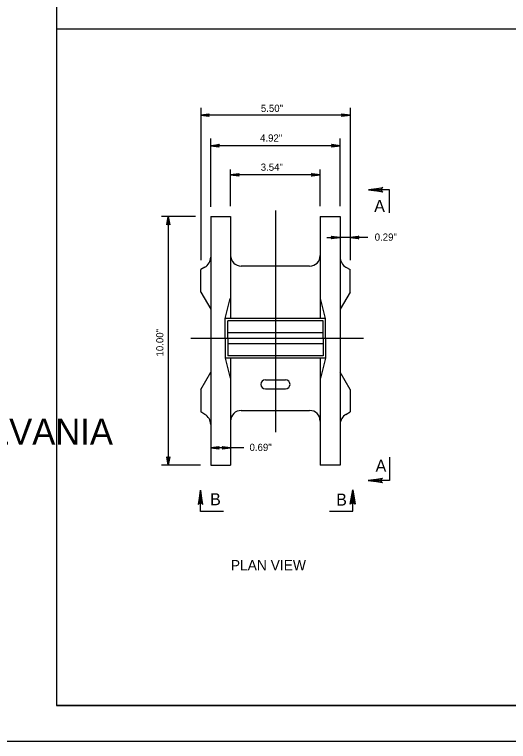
# Model space of a CAD drawing. Extents: x 639362 to 641108, y 298458 to 299646.
# Drawn here: x 640225.9 to 640431.7, y 298457.6 to 298760.6 of the extents above; entities that cross this region are included whole.
import ezdxf

# ---------------------------------------------------------------- set-up
doc = ezdxf.new("R2010")
doc.units = 0
for name, color, linetype in [('1', 7, 'Continuous'), ('2', 7, 'Continuous'), ('3', 7, 'Continuous'), ('PLT-BNDY', 7, 'Continuous')]:
    doc.layers.add(name, color=color, linetype=linetype)

# ---------------------------------------------------------------- blocks, each defined once
blk = doc.blocks.new('RARROW')
at = {"layer": '3'}
blk.add_lwpolyline([(-2.2695, 0.285), (-2.184875, 0.12075), (0, 0), (-2.2695, 0.285), (-2.38575, 0.384625), (0, 0), (-2.183125, -0.108), (-2.262875, -0.2705), (0, 0), (-2.38575, -0.379125), (-2.262875, -0.2705)], dxfattribs=at)

msp = doc.modelspace()

# ---------------------------------------------------------------- linework, layer by layer
at = {"layer": '1'}
for p, q in [((640243.31, 299036.63), (640243.31, 298472.63)), ((640243.31, 298754.63), (640829.31, 298754.63)), ((641029.31, 298472.63), (640243.31, 298472.63)), ((640243.31, 298472.63), (640829.31, 298472.63))]:
    msp.add_line(p, q, dxfattribs=at)
at = {"layer": '2'}
for p, q in [((640303.46, 298721.7), (640303.46, 298658.32)), ((640365.72, 298721.7), (640365.72, 298658.32)), ((640365.72, 298718.7), (640303.46, 298718.7)), ((640307.61, 298680.52), (640307.61, 298708.97)), ((640361.56, 298680.82), (640361.56, 298708.97)), ((640361.56, 298705.97), (640307.61, 298705.97)), ((640315.91, 298680.82), (640315.91, 298696.07)), ((640353.26, 298680.82), (640353.26, 298696.07)), ((640353.26, 298693.8), (640315.91, 298693.8)), ((640382.2, 298687.58), (640373.32, 298687.58)), ((640382.2, 298677.95), (640382.2, 298687.58)), ((640334.59, 298678.97), (640334.59, 298586.59)), ((640301.31, 298676.52), (640287.16, 298676.52)), ((640289.95, 298676.52), (640289.95, 298572.76)), ((640307.61, 298676.52), (640307.61, 298572.76)), ((640307.61, 298676.52), (640315.91, 298676.52)), ((640315.91, 298676.52), (640315.91, 298633.98)), ((640353.26, 298676.52), (640361.56, 298676.52)), ((640353.26, 298676.52), (640353.26, 298633.98)), ((640361.56, 298676.52), (640361.56, 298572.76)), ((640355.97, 298667.66), (640361.4, 298667.66)), ((640365.72, 298667.66), (640361.64, 298667.66)), ((640373.13, 298667.66), (640365.72, 298667.66)), ((640305.17, 298655.31), (640303.46, 298654.32)), ((640348.84, 298655.77), (640320.34, 298655.77)), ((640364, 298655.31), (640365.72, 298654.32)), ((640303.46, 298644.96), (640303.46, 298654.32)), ((640365.72, 298644.96), (640365.72, 298654.32)), ((640303.46, 298644.96), (640307.61, 298637.77)), ((640365.72, 298644.96), (640361.56, 298637.77)), ((640313.66, 298633.98), (640315.77, 298642.33)), ((640355.51, 298633.98), (640353.4, 298642.33)), ((640355.51, 298633.98), (640313.66, 298633.98)), ((640313.66, 298625.68), (640313.66, 298633.98)), ((640355.51, 298625.68), (640355.51, 298633.98)), ((640314.72, 298625.68), (640314.72, 298632.99)), ((640354.46, 298632.99), (640314.72, 298632.99)), ((640354.46, 298625.68), (640354.46, 298632.99)), ((640354.46, 298628.01), (640314.72, 298628.01)), ((640299.32, 298625.68), (640371.31, 298625.68)), ((640313.66, 298625.68), (640313.66, 298617.38)), ((640314.72, 298625.68), (640314.72, 298618.38)), ((640354.46, 298625.68), (640354.46, 298618.38)), ((640355.51, 298625.68), (640355.51, 298617.38)), ((640354.46, 298623.36), (640314.72, 298623.36)), ((640354.46, 298618.38), (640314.72, 298618.38)), ((640355.51, 298617.38), (640313.66, 298617.38)), ((640313.66, 298617.38), (640315.77, 298609.04)), ((640315.91, 298617.38), (640315.91, 298572.76)), ((640353.26, 298617.38), (640353.26, 298572.76)), ((640355.51, 298617.38), (640353.4, 298609.04)), ((640303.46, 298604.32), (640307.61, 298611.52)), ((640365.72, 298604.32), (640361.56, 298611.52)), ((640330.41, 298608.39), (640338.77, 298608.39)), ((640303.46, 298604.32), (640303.46, 298594.97)), ((640330.41, 298604.58), (640338.77, 298604.58)), ((640365.72, 298604.32), (640365.72, 298594.97)), ((640305.17, 298593.98), (640303.46, 298594.97)), ((640320.34, 298595.59), (640348.84, 298595.59)), ((640364, 298593.98), (640365.72, 298594.97)), ((640315.91, 298580.01), (640307.61, 298580.01)), ((640321.42, 298580.01), (640315.91, 298580.01)), ((640382.08, 298576.2), (640382.08, 298566.45)), ((640303.31, 298572.76), (640287.16, 298572.76)), ((640307.61, 298572.76), (640315.91, 298572.76)), ((640361.56, 298572.76), (640353.26, 298572.76)), ((640382.08, 298566.45), (640373.2, 298566.45)), ((640303.35, 298553.53), (640303.35, 298562.4)), ((640366.8, 298553.68), (640366.8, 298562.56)), ((640312.97, 298553.53), (640303.35, 298553.53)), ((640357.17, 298553.68), (640366.8, 298553.68))]:
    msp.add_line(p, q, dxfattribs=at)
for points in [[(640306.86, 298718.27), (640306.74, 298718.52), (640303.46, 298718.7), (640306.86, 298718.27), (640307.04, 298718.12), (640303.46, 298718.7), (640306.73, 298718.86), (640306.85, 298719.1), (640303.46, 298718.7), (640307.04, 298719.27), (640306.85, 298719.1)], [(640362.31, 298719.12), (640362.44, 298718.88), (640365.72, 298718.7), (640362.31, 298719.12), (640362.14, 298719.27), (640365.72, 298718.7), (640362.44, 298718.53), (640362.32, 298718.29), (640365.72, 298718.7), (640362.14, 298718.13), (640362.32, 298718.29)], [(640311.01, 298705.54), (640310.89, 298705.79), (640307.61, 298705.97), (640311.01, 298705.54), (640311.19, 298705.39), (640307.61, 298705.97), (640310.88, 298706.13), (640311, 298706.38), (640307.61, 298705.97), (640311.19, 298706.54), (640311, 298706.38)], [(640358.16, 298706.4), (640358.29, 298706.15), (640361.56, 298705.97), (640358.16, 298706.4), (640357.98, 298706.54), (640361.56, 298705.97), (640358.29, 298705.81), (640358.17, 298705.56), (640361.56, 298705.97), (640357.98, 298705.4), (640358.17, 298705.56)], [(640319.32, 298693.37), (640319.19, 298693.62), (640315.91, 298693.8), (640319.32, 298693.37), (640319.49, 298693.22), (640315.91, 298693.8), (640319.19, 298693.96), (640319.3, 298694.2), (640315.91, 298693.8), (640319.49, 298694.37), (640319.3, 298694.2)], [(640349.86, 298694.22), (640349.99, 298693.98), (640353.26, 298693.8), (640349.86, 298694.22), (640349.68, 298694.37), (640353.26, 298693.8), (640349.99, 298693.63), (640349.87, 298693.39), (640353.26, 298693.8), (640349.68, 298693.23), (640349.87, 298693.39)], [(640289.52, 298673.12), (640289.77, 298673.24), (640289.95, 298676.52), (640289.52, 298673.12), (640289.38, 298672.94), (640289.95, 298676.52), (640290.12, 298673.25), (640290.36, 298673.13), (640289.95, 298676.52), (640290.52, 298672.94), (640290.36, 298673.13)], [(640358, 298668.08), (640358.12, 298667.84), (640361.4, 298667.66), (640358, 298668.08), (640357.82, 298668.23), (640361.4, 298667.66), (640358.13, 298667.49), (640358.01, 298667.25), (640361.4, 298667.66), (640357.82, 298667.09), (640358.01, 298667.25)], [(640369.12, 298667.23), (640369, 298667.48), (640365.72, 298667.66), (640369.12, 298667.23), (640369.3, 298667.08), (640365.72, 298667.66), (640368.99, 298667.82), (640369.11, 298668.06), (640365.72, 298667.66), (640369.3, 298668.23), (640369.11, 298668.06)], [(640311.01, 298579.58), (640310.89, 298579.83), (640307.61, 298580.01), (640311.01, 298579.58), (640311.19, 298579.43), (640307.61, 298580.01), (640310.89, 298580.17), (640311, 298580.42), (640307.61, 298580.01), (640311.19, 298580.58), (640311, 298580.42)], [(640312.51, 298580.44), (640312.63, 298580.19), (640315.91, 298580.01), (640312.51, 298580.44), (640312.33, 298580.59), (640315.91, 298580.01), (640312.64, 298579.85), (640312.52, 298579.61), (640315.91, 298580.01), (640312.33, 298579.44), (640312.52, 298579.61)], [(640290.38, 298576.17), (640290.13, 298576.04), (640289.95, 298572.76), (640290.38, 298576.17), (640290.53, 298576.34), (640289.95, 298572.76), (640289.79, 298576.04), (640289.55, 298576.16), (640289.95, 298572.76), (640289.38, 298576.34), (640289.55, 298576.16)]]:
    msp.add_lwpolyline(points, dxfattribs=at)
for centre, radius, start, end in [((640302.74, 298659.52), 4.87, 300.0116, 0), ((640320.34, 298660.2), 4.43, 180, 270), ((640348.83, 298660.2), 4.43, 270, 0), ((640366.43, 298659.53), 4.87, 180, 239.9911), ((640330.41, 298606.49), 1.91, 90, 270), ((640338.77, 298606.49), 1.91, 270, 90), ((640320.34, 298591.16), 4.43, 90, 180), ((640348.83, 298591.16), 4.43, 0, 90), ((640302.74, 298589.76), 4.87, 0, 59.9884), ((640366.43, 298589.76), 4.87, 120.0089, 180)]:
    msp.add_arc(centre, radius, start, end, dxfattribs=at)
at = {"layer": 'PLT-BNDY'}
msp.add_lwpolyline([(640203.31, 299051.63), (641044.31, 299051.63), (641044.31, 298457.63), (640203.31, 298457.63)], close=True, dxfattribs=at)

# ---------------------------------------------------------------- block references
at = {"layer": '2', "xscale": 2.5148695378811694}
for p, yscale, rotation in [((640373.32, 298687.58), 2.618592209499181, 180), ((640373.2, 298566.45), 2.618592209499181, 180), ((640303.35, 298562.4), -2.618592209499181, 90.00000000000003), ((640366.8, 298562.56), 2.618592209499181, 89.99999999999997)]:
    msp.add_blockref('RARROW', p, dxfattribs=dict(at, yscale=yscale, rotation=rotation))

# ---------------------------------------------------------------- texts
at = {"layer": '1'}
msp.add_text('COMMONWEALTH OF PENNSYLVANIA', height=10.7828, dxfattribs=at).set_placement((640000.9, 298581.36))
at = {"layer": '2'}
for s, height, p in [('5.50"', 3, (640328.53, 298720.05)), ('4.92"', 3, (640328.19, 298707.67)), ('3.54"', 3, (640328.47, 298695.52)), ('A', 5, (640375.77, 298678.35)), ('0.29"', 3, (640375.97, 298666.37)), ('0.69"', 3, (640323.81, 298578.73)), ('A', 5, (640376.35, 298570.08)), ('B', 5, (640307.37, 298556.1)), ('B', 5, (640359.92, 298555.95)), ('PLAN VIEW', 4.3, (640316, 298528.96))]:
    msp.add_text(s, height=height, dxfattribs=at).set_placement(p)
msp.add_text('10.00"', height=3, rotation=90, dxfattribs=at).set_placement((640287.9, 298618.11))

doc.saveas('drawing.dxf')
